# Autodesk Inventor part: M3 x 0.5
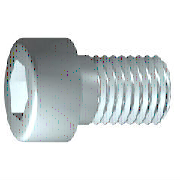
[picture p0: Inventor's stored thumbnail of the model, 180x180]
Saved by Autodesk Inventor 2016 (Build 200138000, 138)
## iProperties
IsCustomPart: 0
Created: 2015-10
Part Number: M3 x 0.5
Material: Steel, Mild
Description: 6각머리 태핑 나사
Document SubType Name: Modeling
Standard: KS B 1003
Designer: mdu
Standards Organization: KS
Language: ko-KR
Size Designation: M 3 x 12
Categories: <MemberInstance><Categories><Category DisplayName="조임쇠" InternalName="e4da775c-781d-43d5-af7c-5136215cf5a6" Mnemonic="FSTN"><Category DisplayName="볼트" InternalN
Density: 1 g/cm^3
Appearance: Steel
Author: mdu
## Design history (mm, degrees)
revolve "본체" stored, may be unused: angle "d10" = 90 deg
sketch "스케치2"
  geometry: L1 (0, -3.85)-(0, 3.85) reference; L2 (-3.85, 0)-(3.85, 0) reference; L3 (1.443, 0)-(0.722, -1.25); L4 (0.722, -1.25)-(-0.722, -1.25); L5 (-0.722, -1.25)-(-1.443, 0); L6 (-1.443, 0)-(-0.722, 1.25); L7 (-0.722, 1.25)-(0.722, 1.25); L8 (0.722, 1.25)-(1.443, 0); 2 further points
  constraints: 12 end point, 1 coincident, 1 horizontal alignment, 1 point on line, 12 other
extrude "슬롯" join sketch "스케치2" stored distance "d11" = 10; taper "d12" = 0 deg
workplane "Work Plane1"
fillet "Fillet2" dims "d30" = 0.1 (= R)
body "Solid1"
fillet "모깎기1" dims "d17" = 0.3 (= RR)
feature "스레드" dims "d13" = 10.75 (= GEL), "d14" = 0
chamfer "모따기1" distance "d15" = 0.30673 (= -0.5 x SPD + 0.5 x GD); stored, may be unused: second distance "d16" = 0.30673 (= GUL), angle "d27" = 45 deg
sketch "스케치1"
  geometry: L1 (-0.867, 0)-(12, 0); L2 (12, 0)-(12, 1.5); L3 (12, 1.5)-(1.25, 1.5); L4 (1.25, 1.5)-(0.943, 1.5); L5 (0.943, 1.5)-(0, 1.5); L6 (0, 1.5)-(0, 2.75); L7 (0, 2.75)-(-3, 2.75); L8 (-3, 2.75)-(-3, 1.443); L9 (-3, 1.443)-(-1.7, 1.443); L10 (-1.7, 1.443)-(-0.867, 0); L11 (-6, 0)-(15, 0) reference; L12 (0, -0.55)-(0, 3.3) reference; L13 (1.25, 1.5)-(0, 1.5)
  constraints: 22 end point, 6 parallel, 2 collinear, 2 perpendicular, 1 horizontal, 1 point on line
  dimensions: "d1" = 10.75 distance from line of L3.end L2 (= GEL); "d2" = 0.30683 distance of L4.end L3.end (computed from GAL); "d3" = 3 distance between parallel lines of L8 L6 (= KOH); "d4" = 1.3 distance of L8.end L9.end (= INTI); "d5" = 60 deg angle of L10 L1; "d6" = 3 diameter of L3 L1 (= GD); "d7" = 3 diameter of L5 L1 (= BDM); "d8" = 2.88675 diameter of L9 L1 (= 1.1547 x SW); "d9" = 5.5 diameter of L7 L1 (= KOD); "d26" = 12 distance between parallel lines of L12 L2 (= NLG)
other parameters: "GD" = 3 (= NND) [user parameter; used in 2 equation terms], "NLG" = 12 [user parameter; used in 1 equation term], "GEL" = 10.75 [user parameter; used in 2 equation terms], "KOD" = 5.5 [user parameter; used in 1 equation term], "KOH" = 3 [user parameter; used in 1 equation term], "INTI" = 1.3 [user parameter; used in 1 equation term], "GAL" = 0.30673 (= 0.61345 x PTC) [user parameter; used in 1 equation term], "GUL" = 0.30673 (= 0.61345 x PTC) [user parameter; used in 1 equation term], "BDM" = 3 (= NND) [user parameter; used in 1 equation term], "SW" = 2.5 [user parameter; used in 2 equation terms], "RR" = 0.3 [user parameter; used in 1 equation term], "SPD" = 2.38655 (= NND - 1.2269 x PTC) [user parameter; used in 1 equation term], "d19" = 0, "d28" = 0, "d29" = 0, "R" = 0.1 [user parameter; used in 1 equation term], "PHH" = 0.1 [user parameter], "GD1" = 2.38655 (= THREADDIA - 1.2269 x PTC) [user parameter], "THREADDIA" = 3 [user parameter; used in 1 equation term], "FAWI" = 45 deg [user parameter], "PTC" = 0.5 [user parameter; used in 5 equation terms], "NND" = 3 [user parameter; used in 3 equation terms], "TOA" = 30 deg [user parameter], "E0" = 2.8875 (= 1.155 x SW) [user parameter]
